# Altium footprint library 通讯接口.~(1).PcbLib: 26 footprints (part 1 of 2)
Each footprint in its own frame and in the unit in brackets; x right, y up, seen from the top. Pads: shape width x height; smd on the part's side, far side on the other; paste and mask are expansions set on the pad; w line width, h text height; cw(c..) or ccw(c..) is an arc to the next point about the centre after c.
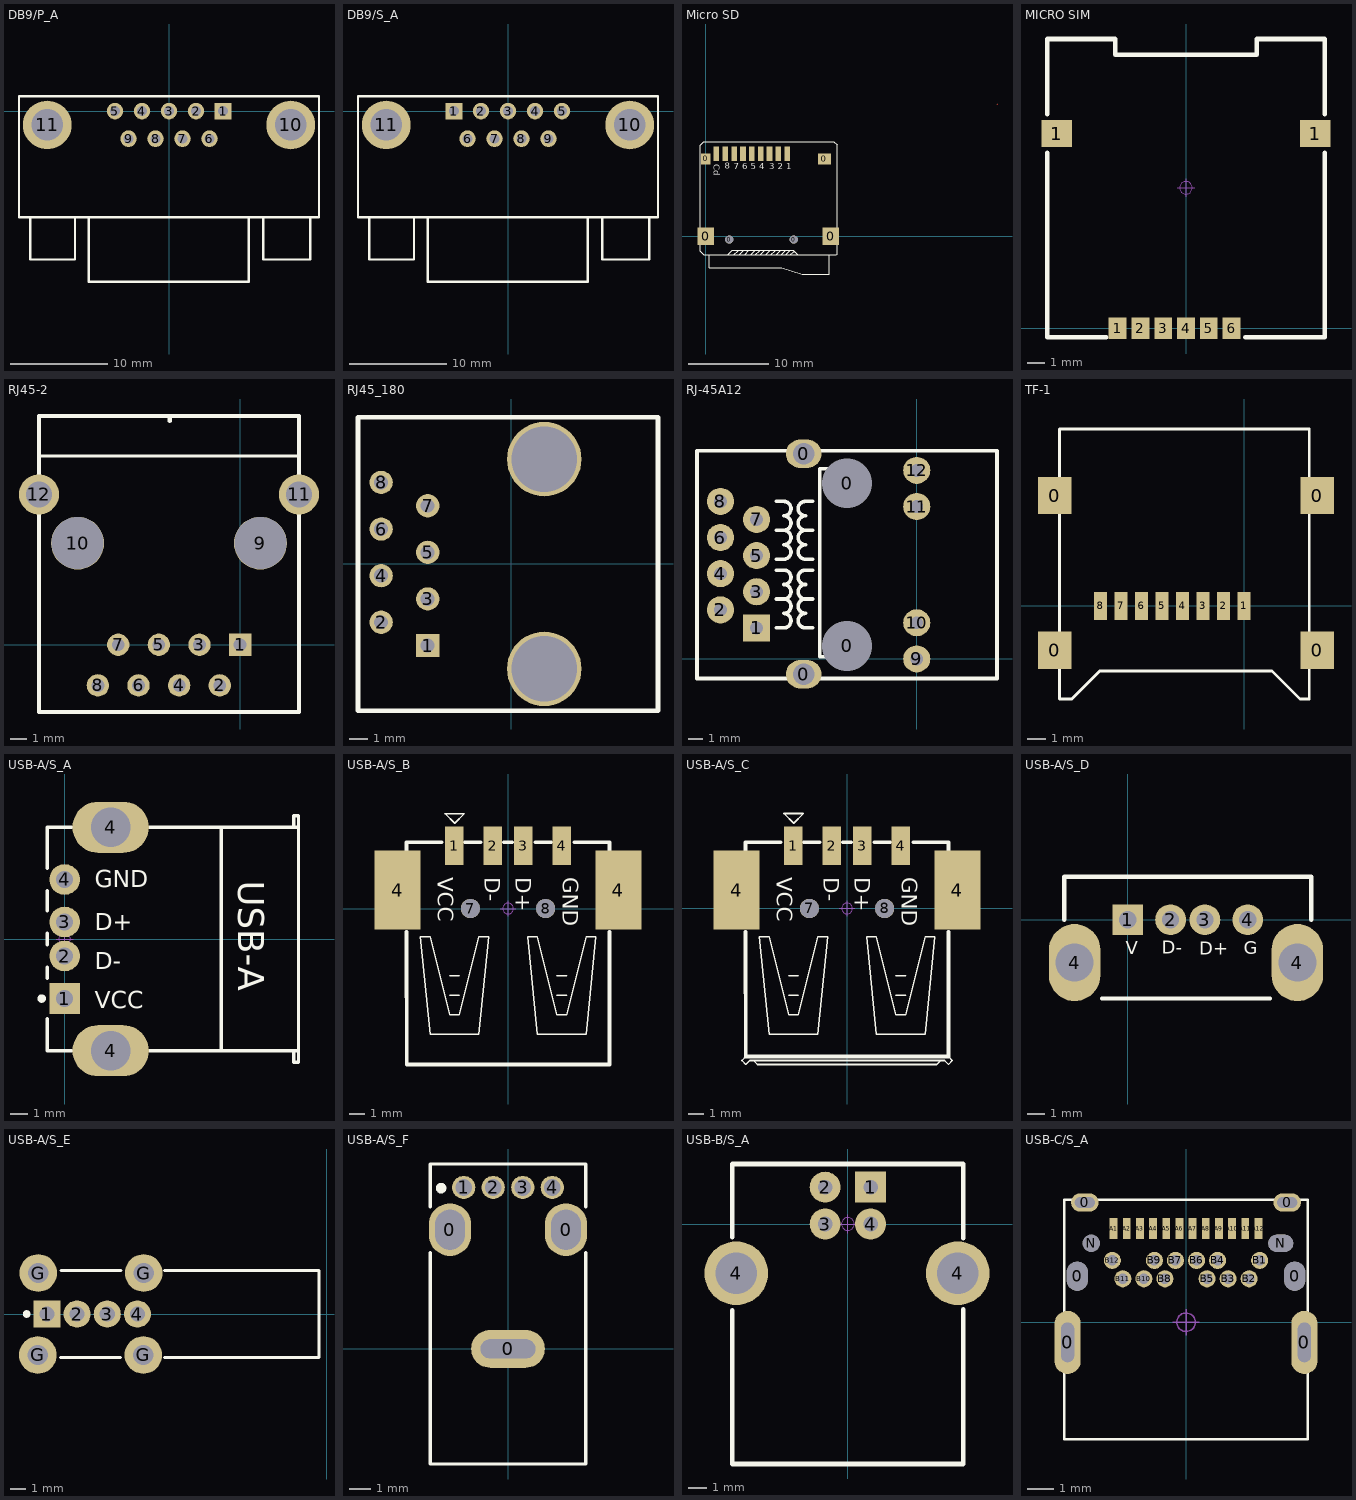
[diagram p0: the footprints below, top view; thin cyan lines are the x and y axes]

## DB9/P_A [mm] "9针公头串口,31*18.5*12.5mm"
pads (11):
  rect 1.7x1.7 hole 1: 1(5.546,0)
  round 1.7 hole 1: 2(2.773,0) 3(0,0) 4(-2.773,0) 5(-5.546,0) 6(4.155,-2.84) 7(1.385,-2.84) 8(-1.385,-2.84) 9(-4.155,-2.84)
  round 5 hole 3.25: 10(12.5,-1.42) 11(-12.5,-1.42)
Top Overlay:
  lines w0.254: -14.224,-10.922 -14.224,-15.24 -9.652,-15.24 -9.652,-10.922 ; -8.225,-10.922 -8.225,-17.526 8.175,-17.526 8.175,-10.922 ; 9.652,-10.922 9.652,-15.24 14.478,-15.24 14.478,-10.922 ; -15.4,-10.922 15.4,-10.922 15.4,1.524 -15.4,1.524 -15.4,-10.922
Mechanical 15:
  circle w0.05: c0,0 r0.35
  lines w0.05: -0.5,0 0.5,0 ; 0,-0.5 0,0.5
3D body: height 12.65, standoff -3.16, extent -15.45,-17.247 15.45,1.253

## DB9/S_A [mm] "9针母头串口,31*18.5*12.5mm"
pads (11):
  rect 1.7x1.7 hole 1: 1(-5.546,0)
  round 1.7 hole 1: 2(-2.773,0) 3(0,0) 4(2.773,0) 5(5.546,0) 6(-4.155,-2.84) 7(-1.385,-2.84) 8(1.385,-2.84) 9(4.155,-2.84)
  round 5 hole 3.25: 10(12.5,-1.42) 11(-12.5,-1.42)
Top Overlay:
  lines w0.254: -14.224,-10.922 -14.224,-15.24 -9.652,-15.24 -9.652,-10.922 ; -8.225,-10.922 -8.225,-17.526 8.175,-17.526 8.175,-10.922 ; 9.652,-10.922 9.652,-15.24 14.478,-15.24 14.478,-10.922 ; -15.4,-10.922 15.4,-10.922 15.4,1.524 -15.4,1.524 -15.4,-10.922
Mechanical 15:
  circle w0.05: c0,0 r0.35
  lines w0.05: -0.5,0 0.5,0 ; 0,-0.5 0,0.5
3D body: height 12.65, standoff -3.16, extent -15.45,-17.247 15.45,1.253

## Micro SD [mm]
pads (15):
  rect 2.032x2.2 smd: 0(0,0) 0(15.5,0)
  rect 1.2x1.4 smd: 0(0,9.6)
  round 1 hole 1 unplated: 0(2.9,-0.4) 0(10.9,-0.4)
  rect 1.6x1.4 smd: 0(14.7,9.6)
  rect 0.7x1.8 smd: 1(10.1,10.227) 2(9,10.227) 3(7.9,10.227) 4(6.8,10.227) 5(5.7,10.227) 6(4.6,10.227) 7(3.5,10.227) 8(2.4,10.227) 9(1.3,10.227)
Top Layer:
  lines w0.03: 36.064,16.423 36.114,16.373
Top Overlay:
  lines w0.152: 0.423,-2.295 0.423,-3.87 9.414,-3.87 ; 3.471,-2.295 4.004,-1.762 4.004,-1.736 ; 4.131,-2.295 4.639,-1.787 4.639,-1.736 ; 4.868,-2.295 4.868,-2.219 5.35,-1.736 ; 5.553,-2.295 6.112,-1.736 6.138,-1.736 ; 6.138,-2.295 6.671,-1.762 6.671,-1.736 ; 6.773,-2.295 7.331,-1.736 7.433,-1.736 ; 7.433,-2.295 7.992,-1.736 8.017,-1.736 ; 8.068,-2.295 8.601,-1.762 8.601,-1.736 ; 8.703,-2.295 9.262,-1.736 9.389,-1.736 ; 9.338,-2.295 9.897,-1.736 9.922,-1.736 ; 9.389,-3.87 11.954,-4.683 15.307,-4.683 15.307,-2.321 ; 9.922,-2.295 10.481,-1.736 ; 10.481,-2.295 10.887,-1.889 10.964,-1.889 ; -0.289,-2.295 2.709,-2.295 3.267,-1.736 10.811,-1.736 11.37,-2.295 16.171,-2.295 ; -0.289,-2.295 16.171,-2.295 ; -0.289,-2.295 -0.72,-1.863 -0.72,11.319 -0.289,11.751 15.891,11.751 16.272,11.37 16.272,-2.194 16.171,-2.295
  text "1" at 9.998,8.297 h0.76
  text "2" at 8.906,8.322 h0.76
  text "3" at 7.839,8.322 h0.76
  text "4" at 6.646,8.322 h0.76
  text "5" at 5.579,8.347 h0.76
  text "6" at 4.512,8.347 h0.76
  text "7" at 3.445,8.347 h0.76
  text "8" at 2.328,8.373 h0.76
  text "Cd" at 0.981,8.932 h0.76
3D body: height 1.8, standoff -0.7, extent -0.272,-4.625 16.001,10.569

## MICRO SIM [mm] "16.30mm*14.66mm*1.8mm(长*宽*厚）"
pads (8):
  rect 1.7x1.5 smd: 1(-7.2,10.85) 1(7.2,10.85)
  rect 1x1.2 smd: 1(-3.81,0) 2(-2.54,0) 3(-1.27,0) 4(0,0) 5(1.27,0) 6(2.54,0)
Top Overlay:
  lines w0.254: -7.747,9.779 -7.747,-0.508 -4.445,-0.508 ; -7.747,11.938 -7.747,16.129 -3.937,16.129 -3.937,15.24 3.937,15.24 3.937,16.129 7.747,16.129 7.747,11.938 ; 3.302,-0.508 7.747,-0.508 7.747,9.779
Mechanical 15:
  circle w0.05: c0,7.83 r0.35
  lines w0.05: -0.5,7.83 0.5,7.83 ; 0,7.33 0,8.33
3D body: height 1.85, standoff 0.04, extent -7.58,-0.3 7.58,15.96

## RJ45-2 [mil] "网线接口"
pads (12):
  rect 55x55 hole 31.5: 1(0,0)
  round 55 hole 31.5: 2(-50,-100) 3(-100,0) 4(-150,-100) 5(-200,0) 6(-250,-100) 7(-300,0) 8(-350,-100)
  round 130 hole 127.95 unplated: 9(50,250) 10(-400,250)
  round 98.42 hole 62.99: 11(145,370) 12(-495,370)
Top Overlay:
  lines w8: -488.19,464.57 141.73,464.57
  lines w10: -495,-165.35 144.65,-165.35 145,-165 145,370 145,562.99 -495,562.99 -495,370 -495,-165 ; -173.23,551.18 -173.23,559.06
3D body: height 127.85, standoff -555.12, extent -490,-172.17 139.92,556.17

## RJ45_180 [mil] "网线接口"
height 53.15
pads (10):
  rect 50x50 hole 30: 1(-179.13,-175)
  round 50 hole 30: 2(-279.13,-125) 3(-179.13,-75) 4(-279.13,-25) 5(-179.13,25) 6(-279.13,75) 7(-179.13,125) 8(-279.13,175)
  round 160 hole 140: ""(70.87,-225) ""(70.87,225)
Top Overlay:
  lines w10: -328.74,-314.96 314.96,-314.96 314.96,314.96 -328.74,314.96 -328.74,-314.96
3D body: height 641.73, standoff -129.92, extent -313.88,-296.61 308.16,313.62

## RJ-45A12 [mil] "网线接口"
pads (16):
  oval 98.43x78.74 hole 59.06: 0(-312.99,-42.13) 0(-312.99,567.32)
  round 130 hole 137.8: 0(-192.91,35.83) 0(-192.91,485.83)
  rect 75x75 hole 35.43: 1(-442.91,85.83)
  round 75 hole 35.43: 2(-542.91,135.83) 3(-442.91,185.83) 4(-542.91,235.83) 5(-442.91,285.83) 6(-542.91,335.83) 7(-442.91,385.83) 8(-542.91,435.83) 9(0,0) 10(0,100) 11(0,421.65) 12(0,521.65)
Top Overlay:
  lines w10: -387.91,85.83 -367.91,85.83 ccw(c-367.91,105.83) -367.91,125.83 ccw(c-367.91,145.83) -367.91,165.83 ; -387.91,165.83 -367.91,165.83 ; -387.91,245.83 -367.91,245.83 cw(c-367.91,225.83) -367.91,205.83 cw(c-367.91,185.83) -367.91,165.83 ; -387.91,275.83 -367.91,275.83 ccw(c-367.91,295.83) -367.91,315.83 ccw(c-367.91,335.83) -367.91,355.83 ; -387.91,355.83 -367.91,355.83 ; -387.91,435.83 -367.91,435.83 cw(c-367.91,415.83) -367.91,395.83 cw(c-367.91,375.83) -367.91,355.83 ; -287.91,85.83 -307.91,85.83 cw(c-307.91,105.83) -307.91,125.83 cw(c-307.91,145.83) -307.91,165.83 ; -287.91,165.83 -307.91,165.83 ; -287.91,245.83 -307.91,245.83 ccw(c-307.91,225.83) -307.91,205.83 ccw(c-307.91,185.83) -307.91,165.83 ; -287.91,275.83 -307.91,275.83 cw(c-307.91,295.83) -307.91,315.83 cw(c-307.91,335.83) -307.91,355.83 ; -287.91,355.83 -307.91,355.83 ; -287.91,435.83 -307.91,435.83 ccw(c-307.91,415.83) -307.91,395.83 ccw(c-307.91,375.83) -307.91,355.83 ; -247.91,5.83 -267.91,5.83 -267.91,525.83 -247.91,525.83 ; -607.91,-54.17 222,-54.17 222,575.83 -607.91,575.83 -607.91,-54.17
Multi-Layer:
  text "J10" at -517.7,505.32 h25
3D body: height 59.06, standoff -590.55, extent -605.26,-53 237.26,572.19

## TF-1 [mm]
height 2
pads (12):
  rect 1.8x2 smd: 0(-10.168,-2.378) 0(-10.168,5.922) 0(3.932,-2.378) 0(3.932,5.922)
  rect 0.7x1.5 smd: 1(0,0) 2(-1.1,0) 3(-2.2,0) 4(-3.3,0) 5(-4.4,0) 6(-5.5,0) 7(-6.6,0) 8(-7.7,0)
Top Overlay:
  lines w0.152: -9.9,-5 -9.25,-5 -7.75,-3.5 1.5,-3.5 3,-5 3.5,-5 3.5,9.5 0,9.5 -9.9,9.5 -9.9,-5
3D body: height 1.93, standoff -0.02, extent -10.5,-5 4.1,9.5

## USB-A/S_A [mm] "A型直插母头，"
height 7.01
pads (6):
  rect 1.8x1.8 hole 1: 1(0,-3.5)
  round 1.8 hole 1: 2(0,-1) 3(0,1) 4(0,3.5)
  oval 4.5x3 hole 2.3: 4(2.71,-6.57) 4(2.71,6.57)
Top Overlay:
  circle w0.25: c-1.35,-3.5 r0.125
  lines w0.2: -1.01,-4.7 -1.01,-6.565 0.41,-6.565 ; -1.01,-2.3 -1.01,-1.66 ; -1.01,-0.34 -1.01,0.34 ; -1.01,1.66 -1.01,2.84 ; -1.01,4.16 -1.01,6.565 0.41,6.565 ; 5.01,-6.565 13.752,-6.565 ; 5.01,6.565 13.752,6.565 ; 13.462,-6.565 13.462,-7.25 13.752,-7.25 13.752,7.25 13.462,7.25 13.462,6.565
  lines w0.203: 9.21,-6.565 9.21,6.565
  text "USB-A" at 10.21,3.43 h1.52
  text "VCC" at 1.778,-4.064 h1.02
  text "D-" at 1.778,-1.778 h1.02
  text "D+" at 1.778,0.508 h1.02
  text "GND" at 1.778,3.048 h1.02
Mechanical 15:
  circle w0.05: c0,0 r0.35
  lines w0.05: -0.5,0 0.5,0 ; 0,-0.5 0,0.5
3D body: height 6.8, standoff -4.31, extent -0.605,-7.342 13.7,7.342

## USB-A/S_B [mm] "A型贴片母头，"
pads (8):
  rect 1.2x2.5 smd: 1(-3.5,4.1) 2(-1,4.1) 3(1,4.1) 4(3.5,4.1)
  rect 3x5.15 smd: 4(-7.2,1.2) 4(7.2,1.2)
  round 1.25 hole 1.25 unplated: 7(-2.45,0) 8(2.45,0)
Top Overlay:
  lines w0.1: -3.803,-5.649 -3.168,-5.649 ; -3.803,-4.379 -3.168,-4.379 ; 3.182,-5.649 3.817,-5.649 ; 3.182,-4.379 3.817,-4.379 ; -5.708,-1.839 -5.073,-8.189 -1.898,-8.189 -1.263,-1.839 -1.898,-1.839 -3.168,-6.919 -3.803,-6.919 -5.073,-1.839 -5.708,-1.839 ; -4.113,6.19 -3.478,5.555 -2.843,6.19 -4.113,6.19 ; 1.277,-1.839 1.912,-8.189 5.087,-8.189 5.722,-1.839 5.087,-1.839 3.817,-6.919 3.182,-6.919 1.912,-1.839 1.277,-1.839
  lines w0.254: -6.604,-1.524 -6.597,-10.16 6.611,-10.16 6.604,-1.524 ; -6.604,3.81 -6.604,4.318 -4.318,4.318 ; -2.794,4.318 -1.778,4.318 ; -0.254,4.318 0.254,4.318 ; 1.778,4.318 2.794,4.318 ; 4.318,4.318 6.611,4.318 6.604,3.81
  text "GND" at 3.556,2.032 h1.02
  text "D+" at 0.508,2.032 h1.02
  text "D-" at -1.524,2.032 h1.02
  text "VCC" at -4.572,2.032 h1.02
Mechanical 15:
  circle w0.05: c0,0 r0.35
  lines w0.05: -0.5,0 0.5,0 ; 0,-0.5 0,0.5
3D body: height 6.9, standoff -0.55, extent -7.75,-9.9 7.75,4.8

## USB-A/S_C [mm] "A型贴片母头，"
pads (8):
  rect 1.2x2.5 smd: 1(-3.5,4.1) 2(-1,4.1) 3(1,4.1) 4(3.5,4.1)
  rect 3x5.15 smd: 4(-7.2,1.2) 4(7.2,1.2)
  round 1.25 hole 1.25 unplated: 7(-2.45,0) 8(2.45,0)
Top Overlay:
  lines w0.1: -6.597,-9.652 -6.851,-9.906 -6.597,-10.16 -6.343,-9.906 -6.089,-9.906 ; -3.803,-5.649 -3.168,-5.649 ; -3.803,-4.379 -3.168,-4.379 ; 3.182,-5.649 3.817,-5.649 ; 3.182,-4.379 3.817,-4.379 ; 6.611,-9.652 6.865,-9.906 6.611,-10.16 6.357,-9.906 6.103,-9.906 ; -6.089,-9.906 -5.835,-10.166 5.849,-10.166 6.103,-9.906 ; -6.089,-9.906 6.103,-9.906 ; -5.708,-1.839 -5.073,-8.189 -1.898,-8.189 -1.263,-1.839 -1.898,-1.839 -3.168,-6.919 -3.803,-6.919 -5.073,-1.839 -5.708,-1.839 ; -4.113,6.19 -3.478,5.555 -2.843,6.19 -4.113,6.19 ; 1.277,-1.839 1.912,-8.189 5.087,-8.189 5.722,-1.839 5.087,-1.839 3.817,-6.919 3.182,-6.919 1.912,-1.839 1.277,-1.839
  lines w0.254: -6.604,-1.524 -6.597,-9.652 ; -6.604,3.81 -6.604,4.318 -4.318,4.318 ; -6.597,-9.652 6.611,-9.652 ; -2.794,4.318 -1.778,4.318 ; -0.254,4.318 0.254,4.318 ; 1.778,4.318 2.794,4.318 ; 4.318,4.318 6.611,4.318 6.604,3.81 ; 6.604,-1.524 6.611,-9.652
  text "GND" at 3.556,2.032 h1.02
  text "D+" at 0.508,2.032 h1.02
  text "D-" at -1.524,2.032 h1.02
  text "VCC" at -4.572,2.032 h1.02
Mechanical 15:
  circle w0.05: c0,0 r0.35
  lines w0.05: -0.5,0 0.5,0 ; 0,-0.5 0,0.5
3D body: height 7.4, standoff -0.55, extent -7.75,-9.9 7.75,4.8

## USB-A/S_D [mm] "A型直插母头，"
pads (6):
  rect 1.8x1.8 hole 1: 1(0,0)
  round 1.8 hole 1: 2(2.5,0) 3(4.5,0) 4(7,0)
  oval 3x4.5 hole 2.2: 4(-3.1,-2.5) 4(9.9,-2.5)
Top Overlay:
  lines w0.254: -3.7,0 -3.7,2.5 10.7,2.5 10.7,0 ; -1.5,-4.6 8.3,-4.6
  text "V" at -0.112,-2.007 h0.76
  text "G" at 6.771,-2.007 h0.76
  text "D+" at 4.181,-2.032 h0.76
  text "D-" at 1.996,-1.981 h0.76
Mechanical 1:
  lines w0.254: -0.2,-0.2 cw(c0,-0.2) 0,0
3D body: height 14, standoff -4, extent -3.705,-4.599 10.695,2.501

## USB-A/S_E [mm] "A型直插母头，"
pads (8):
  rect 1.8x1.8 hole 1: 1(-18.56,0)
  round 1.8 hole 1: 2(-16.56,0) 3(-14.56,0) 4(-12.56,0)
  round 2.5 hole 1.35: G(-19.167,-2.718) G(-19.141,2.718) G(-12.167,-2.718) G(-12.141,2.718)
Top Overlay:
  circle w0.25: c-19.91,0 r0.125
  lines w0.2: -17.65,-2.878 -13.684,-2.878 ; -17.624,2.878 -13.658,2.878 ; -10.773,-2.88 -0.508,-2.88 -0.508,2.88 -10.773,2.88
3D body: height 14.45, standoff -3.69, extent -19.725,-3.606 -0.475,3.644

## USB-A/S_F [mm] "A型侧插短体无卷边 90度母座"
pads (7):
  oval 2x2.5 hole 1.4 slot 1.9 at 90 deg: 0(-2.75,5.65) 0(2.75,5.65)
  oval 3.5x1.8 hole 0.9 slot 2.6 at 0 deg: 0(0,0)
  round 1.1 hole 0.8: 1(-2.1,7.65) 2(-0.7,7.65) 3(0.7,7.65) 4(2.1,7.65)
Top Overlay:
  circle w0.25: c-3.173,7.62 r0.125
  lines w0.152: -3.683,4.572 -3.683,-5.461 3.683,-5.461 3.683,4.572 ; -3.683,6.731 -3.683,8.763 3.683,8.763 3.683,6.731
3D body: height 13.7, standoff -3.05, extent -3.56,-5.35 3.56,8.65

## USB-B/S_A [mm] "b型USB 母座 16.3*13.7*11mm"
height 1.1
pads (6):
  rect 1.7x1.7 hole 0.8: 1(1.25,2.032)
  round 1.7 hole 0.8: 2(-1.25,2.032) 3(-1.25,0) 4(1.25,0)
  round 3.5 hole 2.3: 4(-6.141,-2.71) 4(6.051,-2.71)
Top Overlay:
  lines w0.254: -6.35,-4.737 -6.35,-13.208 6.35,-13.208 6.35,-4.686 ; -6.35,-0.724 -6.35,3.302 6.35,3.302 6.35,-0.775
Mechanical 15:
  circle w0.05: c0,0 r0.35
  lines w0.05: -0.5,0 0.5,0 ; 0,-0.5 0,0.5
3D body: height 11.45, standoff -2.95, extent -6.86,-13.16 6.859,3.14

## USB-C/S_A [mm]
pads (32):
  oval 1x2.4 hole 0.5 slot 1.5 at 90 deg: 0(-4.5,-0.765) 0(4.5,-0.765)
  oval 0.8x1.1 hole 0.8 slot 1.1 at 90 deg: 0(-4.13,1.75) 0(4.13,1.75)
  oval 1.05x0.7 hole 0.4 slot 0.75 at 0 deg: 0(-3.845,4.55) 0(3.845,4.55)
  rect 0.3x0.8 smd: A1(-2.75,3.56) A2(-2.25,3.56) A3(-1.75,3.56) A4(-1.25,3.56) A5(-0.75,3.56) A6(-0.25,3.56) A7(0.25,3.56) A8(0.75,3.56) A9(1.25,3.56) A10(1.75,3.56) A11(2.25,3.56) A12(2.75,3.56)
  round 0.65 hole 0.4: B1(2.8,2.35) B2(2.4,1.65) B3(1.6,1.65) B4(1.2,2.35) B5(0.8,1.65) B6(0.4,2.35) B7(-0.4,2.35) B8(-0.8,1.65) B9(-1.2,2.35) B10(-1.6,1.65) B11(-2.4,1.65) B12(-2.8,2.35)
  round 0.65 hole 0.65: N(-3.6,3)
  oval 0.95x0.65 hole 0.65 slot 0.95 at 0 deg: N(3.6,3)
Top Overlay:
  lines w0.1: -4.625,-4.45 -4.625,4.65 4.625,4.65 4.625,-4.45 -4.625,-4.45
Mechanical 15:
  circle w0.05: c0,0 r0.35
  lines w0.05: -0.5,0 0.5,0 ; 0,-0.5 0,0.5
3D body: height 3.35, standoff -0.9, extent -4.625,-4.45 4.625,4.65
